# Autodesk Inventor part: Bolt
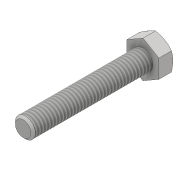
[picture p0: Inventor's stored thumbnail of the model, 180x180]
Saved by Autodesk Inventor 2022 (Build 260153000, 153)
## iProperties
Created: 2016-05
Part Number: Bolt
Material: Generic
Document SubType Name: Modeling
Designer: CADCIM
Density: 1 g/cm^3
Appearance: Default
Author: CADCIM
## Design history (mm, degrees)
sketch "Sketch1"
  geometry: L1 (3.604, -2.072)-(0.007, -4.157); L2 (0.007, -4.157)-(-3.596, -2.085); L3 (-3.596, -2.085)-(-3.604, 2.072); L4 (-3.604, 2.072)-(-0.007, 4.157); L5 (-0.007, 4.157)-(3.596, 2.085); L6 (3.596, 2.085)-(3.604, -2.072); 2 further points
  constraints: 12 end point, 1 coincident, 13 other
  dimensions: "d0" = 7.2 distance between parallel lines of L3 L6
extrude "Extrusion1" new body sketch "Sketch1" distance "d1" = 3.15; taper "d2" = 0 deg
sketch "Sketch2"
  geometry: C1 r 2.25 at (0, 0); 1 further point
  constraints: 1 centre point, 1 coincident
  dimensions: "d3" = 4.5 diameter of C1
extrude "Extrusion2" join sketch "Sketch2" distance "d4" = 27; taper "d5" = 0 deg
thread "Thread1" dims "d6" = 10, "d7" = 0
chamfer "Chamfer1" distance "d8" = 0.5; stored, may be unused: second distance "d9" = 2, angle "d10" = 45 deg
sketch "Sketch3"
  geometry: L1 (0.007, -4.157)-(3.604, -2.072) reference; C1 r 3.6 at (0, 0); 1 further point
  constraints: 1 centre point, 1 coincident, 1 tangent
extrude "Extrusion3" sketch "Sketch3" distance "d11" = 41; taper "d12" = 60 deg
body "Solid1"
